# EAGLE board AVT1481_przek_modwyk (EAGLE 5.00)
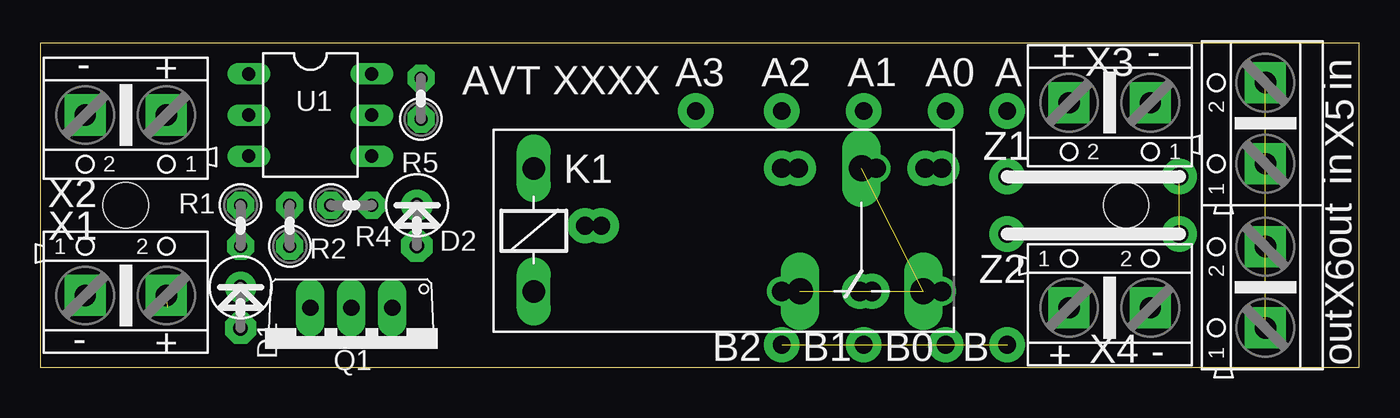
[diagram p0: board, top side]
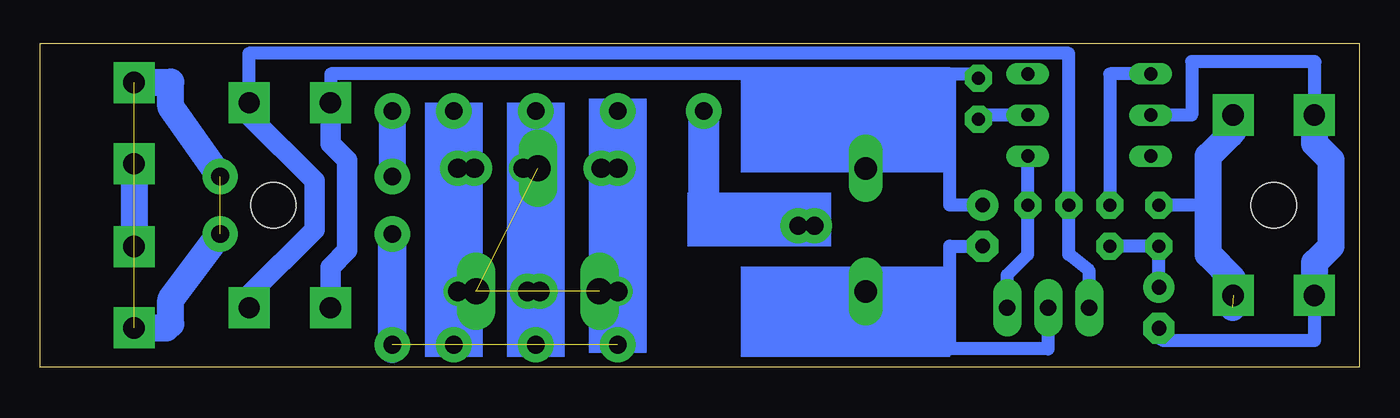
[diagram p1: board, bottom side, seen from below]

Size 81.71 x 20.06 mm. Coordinates in mm from the lower left corner, seen from the top.
Outline: 0,0 81.71,0 81.71,20.06 0,20.06 0,0
Copper layers (1*16): Top 0.035mm / dielectric 1.5mm / Bottom 0.035mm
Design rules "default": minimum track width 10mil, minimum drill 24mil, track to track 32mil, track to pad 8mil, pad to pad 8mil, via to via 8mil, smd to smd 8mil, copper to edge 40mil, drill to drill 8mil, minimum pad ring 10mil, minimum via ring 8mil, stop-mask expansion 4mil, vias tented up to drill 0mil, thermal gap 10mil
Holes 2.8 mm at 5.3,10.03 67.27,10.03

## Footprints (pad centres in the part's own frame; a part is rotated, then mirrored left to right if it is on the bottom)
RAD2,5 = drill 0.9 pad 1.93 octagon: A 1.27,0 | drill 0.9 pad 1.93 round: C -1.27,0
E3206S = drill 1.397 long: 1 -3.175,3.81; 2 -3.175,-3.81 | drill 1.6 long: O 13.335,-3.81; P 17.145,3.81; S 20.955,-3.81
TO220V = drill 1.016 pad 1.778 long: 1 -2.54,-2.54; 2 0,-2.54; 3 2.54,-2.54
0207/2V = drill 0.8 pad 1.676 octagon: 1 -1.27,0; 2 1.27,0
DIL06 = drill 0.813 long: 1 -2.54,-3.81; 2 0,-3.81; 3 2.54,-3.81; 4 2.54,3.81; 5 0,3.81; 6 -2.54,3.81
AK500/2 = drill 1.321 pad 2.54 square: 1 -2.515,0; 2 2.515,0

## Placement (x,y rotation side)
D1  5V1  [RAD2,5]  12.41,3.68 270 top
D2  1N4007  [RAD2,5]  23.33,8.76 270 top
K1  [E3206S]  33.74,8.5 0 top
Q1  BUZ11  [TO220V]  19.27,1.14 180 top
R1  1k  [0207/2V]  12.41,8.76 270 top
R2  1k  [0207/2V]  15.46,8.76 90 top
R4  10k  [0207/2V]  19.27,10.03 0 top
R5  10k  [0207/2V]  23.58,16.63 90 top
U1  CNY17  [DIL06]  16.73,15.62 270 top
X1  ARK500/2DS  [AK500/2]  5.3,4.44 0 top
X2  ARK500/2DS  [AK500/2]  5.3,15.62 180 top
X3  ARK500/2DS  [AK500/2]  66.26,16.38 180 top
X4  ARK500/2DS  [AK500/2]  66.26,3.68 0 top
X5  ARK500/2DS  [AK500/2]  75.91,15.11 90 top
X6  ARK500/2DS  [AK500/2]  75.91,4.95 90 top

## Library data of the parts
D1 D2 = diode
K1 = relay
Q1 = transistor-fet
R1 R2 R4 R5 = rcl
U1 = optocoupler
X1-X6 = con-ptr500

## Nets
N$1: D1.A U1.2 X1.1 X2.2
N$2: R1.1 X1.2 X2.1
N$4: D1.C R1.2 R2.1
N$5: R2.2 U1.1
N$7: R5.1 U1.5
N$8: Q1.1 R4.2 U1.4
N$9: Q1.3 R4.1 X3.1 X4.2
N$10: D2.A K1.2 Q1.2
N$12: D2.C K1.1 R5.2 X3.2 X4.1
N$14: X5.1 X6.2
N$15: K1.O K1.P K1.S X5.2 X6.1

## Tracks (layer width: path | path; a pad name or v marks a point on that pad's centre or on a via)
N$1
  Bottom 0.813: U1.2 10.38,15.62 10.38,18.92 2.76,18.92 2.73,18.89 2.76,18.89 2.76,15.62 | 2.76,15.36 2.76,15.62 | 2.76,15.62 X2.2 | X1.1 2.78,1.67 2.76,1.65 12.15,1.65 12.41,1.9 D1.A
  Bottom 1.676: 2.76,15.36 2.76,13.84 1.74,12.82 1.74,7.49 2.76,6.47 2.76,4.44 X1.1
N$2  (1 unrouted)
  Bottom 0.813: 7.84,3.68 7.86,3.7 | 9.36,10.03 R1.1
  Bottom 1.676: 8.09,14.35 9.36,13.08 9.36,10.03 9.36,6.98 7.84,5.46 7.84,3.68 | 8.09,14.35 7.86,14.58 | X2.1 7.81,14.62 8.09,14.35
N$4
  Bottom 0.813: R2.1 R1.2 D1.C
N$5
  Bottom 0.813: U1.1 15.46,18.16 R2.2 15.2,9.77
N$6  (via drill 1.1 pad 2.18)
  Bottom 1.778: 59.91,1.14 v59.91,8.25
N$7
  Bottom 0.813: U1.5 23.58,15.62 R5.1
N$8
  Bottom 0.813: U1.4 R4.2 20.79,10.03 20.54,9.77 20.54,6.98 21.81,5.71 Q1.1
N$9
  Bottom 0.813: 68.8,16.4 68.8,19.43 18,19.43 R4.1 18.25,9.77 18,9.52 18,6.98 16.73,5.96 Q1.3
  Bottom 1.27: 68.8,16.38 68.8,15.62 64.73,11.55 64.73,8.5 68.8,4.44 | 68.8,4.44 68.82,4.42 | X4.2 68.77,4.42 68.8,4.44 | 68.8,16.38 X3.1 | 68.8,16.4 68.8,16.38
N$10
  Bottom 0.813: 30.44,5.46 K1.2 | 30.44,5.46 30.44,3.42 | 30.44,5.46 30.44,1.14 25.36,1.14 | 25.36,1.14 19.27,1.14 Q1.2 | 25.36,1.14 25.36,7.49 D2.A
N$11  (via drill 1.2 pad 1.42)
  other vias: 51.78,12.31
N$12
  Bottom 0.813: 63.72,16.4 63.72,18.16 25.36,18.16 | 25.36,18.16 23.58,18.16 R5.2 | 25.36,15.87 25.36,10.03 D2.C | 25.36,15.87 25.36,18.16 | K1.1 30.7,13.08 30.7,15.87 25.36,15.87
  Bottom 1.27: 63.72,16.38 63.72,13.84 62.7,12.82 62.7,7.23 63.74,6.19 X4.1 | 63.72,16.38 X3.2 | 63.72,16.4 63.72,16.38
N$13  (via drill 1.1 pad 2.18)  (3 unrouted)
  Bottom 1.676: v59.91,15.87 v59.91,11.81
  other vias: 59.91,1.39 56.1,1.39 51.02,1.39 45.94,1.39 56.1,15.87 51.02,15.87 45.94,15.87 40.6,15.87 33.74,8.76 34.76,8.76 70.57,11.81 70.57,8.25
N$14
  Bottom 1.676: X5.1 X6.2
N$15  (4 unrouted)
  Bottom 1.676: X5.2 73.65,17.62 73.62,17.65 73.62,16.12 70.57,11.81 | X6.1 73.9,2.43 73.62,2.66 73.62,4.19 70.57,8.25
N$17
  Bottom 1.93: 40.6,8.76 40.6,15.87
N$18  (via drill 1.2 pad 1.42)
  other vias: 55.84,4.69
N$19  (via drill 1.2 pad 1.42)
  other vias: 45.94,4.69
N$20  (via drill 1.2 pad 2.18)
  other vias: 46.95,12.31
N$21  (via drill 1.2 pad 2.18)
  other vias: 45.94,12.31
N$22  (via drill 1.2 pad 2.18)
  other vias: 54.83,12.31
N$23  (via drill 1.2 pad 2.18)
  other vias: 55.84,12.31
N$24  (via drill 1.2 pad 2.18)
  other vias: 50.76,4.69
N$25  (via drill 1.2 pad 2.18)
  other vias: 51.52,4.69
(copper drawn outside any net)
  shapes: Bottom area x6

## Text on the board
tPlace: + | - | - | + | A3 | A2 | A1 | A0 | A | AVT XXXX | in | Z1 | in | out | Z2 | - | + | B2 | B1 | B0 | B | + | - | out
